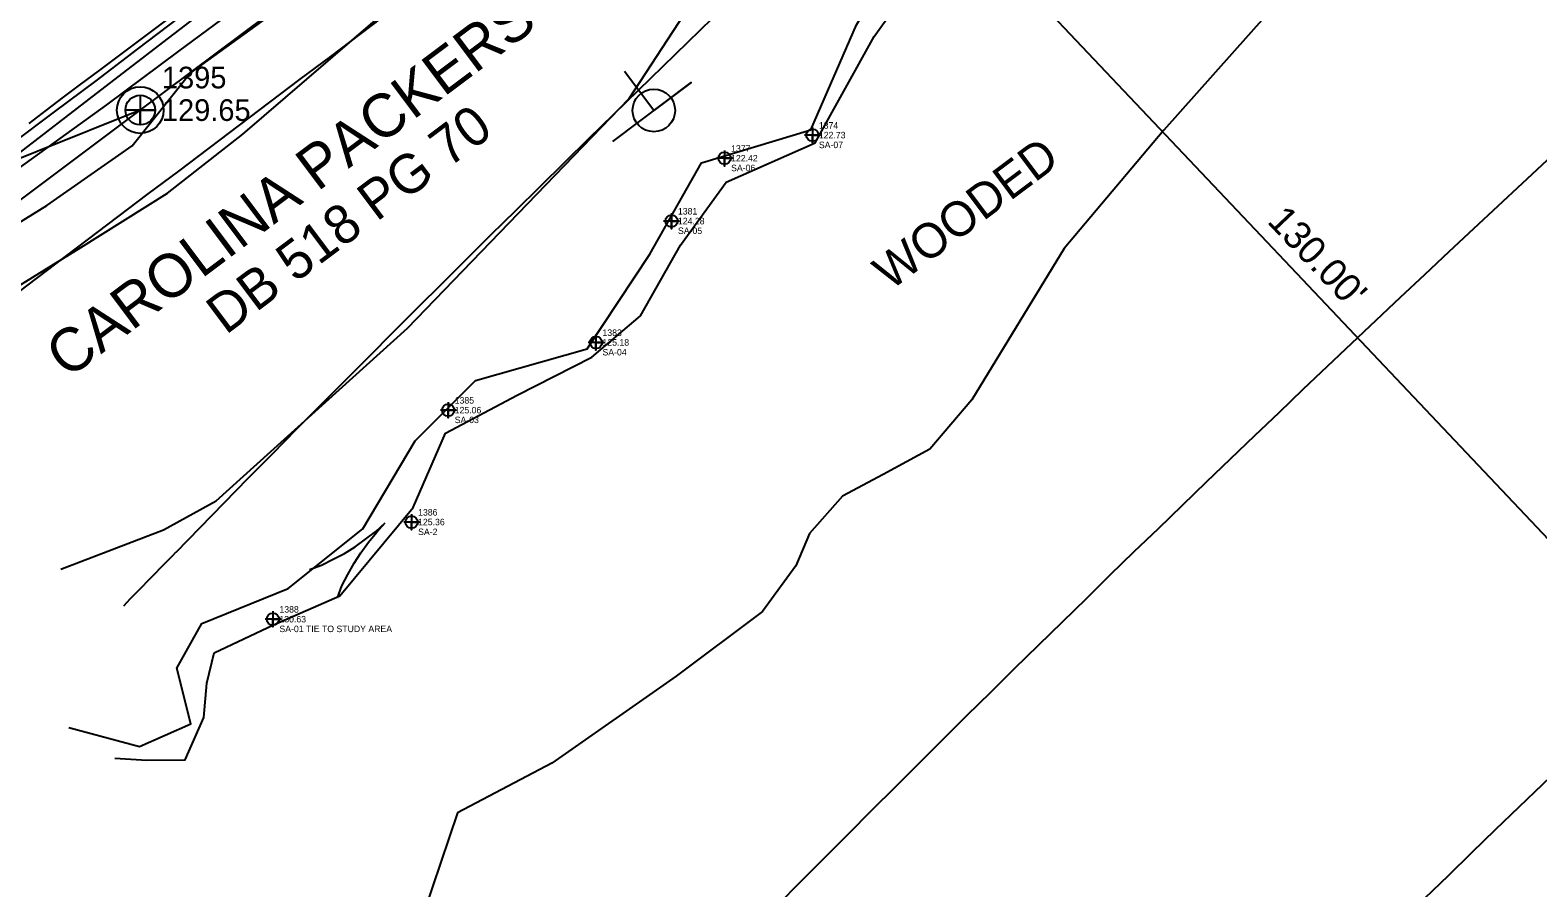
# Model space of a CAD drawing. Extents: x 2186615 to 2188822, y 629899 to 631820.
# Drawn here: x 2186940.8 to 2187114.7, y 630123.7 to 630222.6 of the extents above; entities that cross this region are included whole.
import ezdxf

# ---------------------------------------------------------------- set-up
doc = ezdxf.new("R2010")
doc.units = 0
for name, color, linetype in [('Exist Environmental Wetland Boundary Cogo Comment', 7, 'Continuous'), ('Exist Environmental Wetland Boundary Cogo Elevation', 7, 'Continuous'), ('Exist Environmental Wetland Boundary Cogo Number', 7, 'Continuous'), ('Exist Environmental Wetland Boundary Cogo Point CELL', 7, 'Continuous'), ('Exist Horizontal Alignment', 7, 'Continuous'), ('Exist Hydro Jurisdictional Stream or Body of Water', 7, 'Continuous'), ('Exist Hydro Stream Flow Arrow CELL', 7, 'Continuous'), ('Exist Property Deed Book Text', 7, 'Continuous'), ('Exist Property Owner Text', 7, 'Continuous'), ('Exist Right of Way Line', 7, 'Continuous'), ('Exist Right of Way Width CELL', 7, 'Continuous'), ('Exist Roads EOP', 7, 'Continuous'), ('Exist Roads EOT', 7, 'Continuous'), ('Exist Utilities Power Joint Use Telephone CELL', 7, 'Continuous'), ('Exist Utilities Sanitary Sewer Manhole CELL', 7, 'Continuous'), ('Exist Utilities Sanitary Sewer Manhole Cogo Elevation', 7, 'Continuous'), ('Exist Utilities Sanitary Sewer Manhole Cogo Number', 7, 'Continuous'), ('Exist Utilities Sanitary Sewer Manhole Leader', 7, 'Continuous'), ('Exist Utilities Sanitary Sewer UG Line', 7, 'Continuous'), ('Exist Utilities Telephone UG Cable SUE LOS C', 7, 'Continuous'), ('Exist Utilities Telephone UG FO SUE LOS B', 7, 'Continuous'), ('Exist Vegetation Woods Line', 7, 'Continuous'), ('Exist Vegetation Woods Line Text', 7, 'Continuous'), ('Scratch_Level_1', 7, 'Continuous')]:
    doc.layers.add(name, color=color, linetype=linetype)

msp = doc.modelspace()

# ---------------------------------------------------------------- linework, layer by layer
at = {"layer": 'Exist Environmental Wetland Boundary Cogo Point CELL'}
for points in [[(2187031.03, 630211.35), (2187031.03, 630209.56), (2187031.03, 630210.45), (2187031.93, 630210.45), (2187030.13, 630210.45)], [(2187020.91, 630208.69), (2187020.91, 630206.89), (2187020.91, 630207.79), (2187021.81, 630207.79), (2187020.01, 630207.79)], [(2187014.78, 630201.45), (2187014.78, 630199.65), (2187014.78, 630200.55), (2187015.68, 630200.55), (2187013.88, 630200.55)], [(2187006.08, 630187.45), (2187006.08, 630185.65), (2187006.08, 630186.55), (2187006.98, 630186.55), (2187005.18, 630186.55)], [(2186989.04, 630179.65), (2186989.04, 630177.85), (2186989.04, 630178.75), (2186989.94, 630178.75), (2186988.14, 630178.75)], [(2186984.82, 630166.74), (2186984.82, 630164.95), (2186984.82, 630165.84), (2186985.72, 630165.84), (2186983.92, 630165.84)], [(2186968.83, 630155.55), (2186968.83, 630153.75), (2186968.83, 630154.65), (2186969.73, 630154.65), (2186967.93, 630154.65)]]:
    msp.add_lwpolyline(points, dxfattribs=at)
for centre in [(2187031.03, 630210.45), (2187020.91, 630207.79), (2187014.78, 630200.55), (2187006.08, 630186.55), (2186989.04, 630178.75), (2186984.82, 630165.84), (2186968.83, 630154.65)]:
    msp.add_circle(centre, 0.703, dxfattribs=at)
at = {"layer": 'Exist Horizontal Alignment'}
msp.add_arc((2232330.7, 570095.74), 75342.48, 126.8592631, 127.0730198, dxfattribs=at)
at = {"layer": 'Exist Hydro Jurisdictional Stream or Body of Water'}
for points in [[(2186945.28, 630142.14), (2186953.45, 630139.97), (2186959.37, 630142.56), (2186957.75, 630149), (2186960.65, 630154.13), (2186970.58, 630158.18), (2186979.2, 630165.07), (2186985.24, 630175.2), (2186992.2, 630182.18), (2187005.05, 630185.83), (2187012.27, 630196.73), (2187018.23, 630207.27), (2187030.87, 630211.07), (2187036.12, 630223.16), (2187043.3, 630234.99), (2187052.05, 630246.59), (2187063.94, 630254.24), (2187079.12, 630254.94), (2187084.62, 630265.04), (2187091.95, 630272.3), (2187103.31, 630282.29), (2187113.92, 630297.14), (2187128.08, 630305.06)], [(2186950.59, 630138.61), (2186954.28, 630138.39), (2186958.71, 630138.41), (2186960.85, 630143.3), (2186961.21, 630147.28), (2186962.05, 630150.76), (2186968.9, 630153.99), (2186976.55, 630157.35), (2186984.99, 630167.53), (2186988.72, 630176.1), (2186996.99, 630180.49), (2187005.6, 630184.87), (2187011.23, 630189.6), (2187015.82, 630197.75), (2187021.08, 630205.03), (2187031.34, 630209.56), (2187038.17, 630221.84), (2187054.63, 630244.89)]]:
    msp.add_lwpolyline(points, dxfattribs=at)
at = {"layer": 'Exist Hydro Stream Flow Arrow CELL'}
msp.add_line((2186978.22, 630162.24), (2186978.22, 630162.24), dxfattribs=at)
for points in [[(2186973.05, 630160.37), (2186974.43, 630160.88), (2186975.77, 630161.55), (2186977.08, 630162.22), (2186978.31, 630162.99), (2186979.52, 630163.85), (2186980.69, 630164.77), (2186981.79, 630165.75)], [(2186976.26, 630157.1), (2186976.79, 630158.47), (2186977.48, 630159.8), (2186978.18, 630161.1), (2186978.97, 630162.31), (2186979.85, 630163.51), (2186980.8, 630164.67), (2186981.79, 630165.75)]]:
    msp.add_lwpolyline(points, dxfattribs=at)
at = {"layer": 'Exist Right of Way Line'}
for centre, radius, start, end in [((2189028.8, 628141.74), 2893.55, 125.65722, 135.70821), ((2189028.8, 628141.74), 2763.55, 125.65722, 135.70821), ((2232330.7, 570095.74), 75312.48, 126.8592631, 127.0730198), ((2188984.64, 628184.81), 2831.87, 135.70821, 135.88261)]:
    msp.add_arc(centre, radius, start, end, dxfattribs=at)
at = {"layer": 'Exist Right of Way Width CELL'}
for p in [(2187040.28, 630243.75), (2187129.62, 630149.31)]:
    msp.add_line(p, (2187087.53, 630193.8), dxfattribs=at)
at = {"layer": 'Exist Roads EOP'}
msp.add_lwpolyline([(2186957.96, 630223.97), (2186953.18, 630220.35), (2186948.4, 630216.73), (2186943.62, 630213.12), (2186938.82, 630209.52)], dxfattribs=at)
at = {"layer": 'Exist Roads EOT'}
msp.add_lwpolyline([(2186956.67, 630223.81), (2186954.67, 630222.31), (2186952.66, 630220.82), (2186950.66, 630219.32), (2186948.66, 630217.83), (2186946.66, 630216.33), (2186944.66, 630214.83), (2186942.67, 630213.32), (2186940.67, 630211.81)], dxfattribs=at)
at = {"layer": 'Exist Utilities Power Joint Use Telephone CELL'}
msp.add_line((2187012.75, 630213.3), (2187012.75, 630213.3), dxfattribs=at)
msp.add_lwpolyline([(2187008.03, 630209.7), (2187017.07, 630216.53), (2187012.76, 630213.28), (2187009.35, 630217.77)], dxfattribs=at)
msp.add_circle((2187012.75, 630213.3), 2.45, dxfattribs=at)
at = {"layer": 'Exist Utilities Sanitary Sewer Manhole CELL'}
msp.add_lwpolyline([(2186953.53, 630215.05), (2186953.53, 630211.63), (2186953.53, 630213.34), (2186955.24, 630213.34), (2186951.81, 630213.34)], dxfattribs=at)
for radius in [2.69, 1.71]:
    msp.add_circle((2186953.53, 630213.34), radius, dxfattribs=at)
at = {"layer": 'Exist Utilities Sanitary Sewer Manhole Leader'}
msp.add_lwpolyline([(2186953.53, 630213.34), (2186905.97, 630194.25), (2186869.08, 630166.59)], dxfattribs=at)
at = {"layer": 'Exist Utilities Sanitary Sewer UG Line'}
for p, q in [((2186953.53, 630213.34), (2187280.26, 630457.75)), ((2186647.85, 629984.07), (2186953.53, 630213.34))]:
    msp.add_line(p, q, dxfattribs=at)
at = {"layer": 'Exist Utilities Telephone UG Cable SUE LOS C'}
for points in [[(2186925.08, 630191.44), (2186942.75, 630202.33), (2186952.61, 630209.21), (2186959.24, 630217.54), (2186981.1, 630233.4), (2186988.91, 630240.52)], [(2186929.03, 630186.19), (2186933.47, 630189.36), (2186946.68, 630197.49), (2186956.69, 630203.77), (2186965.35, 630210.55), (2186985.31, 630227.73), (2186993.86, 630234.89)]]:
    msp.add_lwpolyline(points, dxfattribs=at)
at = {"layer": 'Exist Utilities Telephone UG FO SUE LOS B'}
for points in [[(2186921.88, 630195.7), (2186938.73, 630207.73), (2186949, 630215.65), (2186956.78, 630221.62), (2186978.08, 630237.97), (2186986.3, 630243.89)], [(2186922.89, 630194.36), (2186939.61, 630206.67), (2186949.68, 630213.94), (2186957.97, 630220.12), (2186979.26, 630235.89), (2186987.51, 630242.36)]]:
    msp.add_lwpolyline(points, dxfattribs=at)
at = {"layer": 'Exist Vegetation Woods Line'}
for points in [[(2187134.59, 630271.74), (2187127.09, 630263.84), (2187118.72, 630254.03), (2187108.35, 630244.63), (2187099.34, 630237.49), (2187083.15, 630224.07), (2187071.54, 630211.01), (2187060.06, 630197.38), (2187049.4, 630179.92), (2187044.57, 630174.23), (2187039.19, 630171.31), (2187034.5, 630168.82), (2187030.7, 630164.51), (2187029.13, 630160.78), (2187025.28, 630155.53), (2187015.34, 630148.08), (2187000.99, 630138.03), (2186990.13, 630132.3), (2186985.3, 630118.09)], [(2186944.38, 630160.41), (2186956.2, 630164.93), (2186962.27, 630168.27), (2186984.34, 630188.21), (2187009.89, 630214.68), (2187023.3, 630235.22), (2187047.5, 630258.38), (2187065.13, 630270.94)]]:
    msp.add_lwpolyline(points, dxfattribs=at)
at = {"layer": 'Scratch_Level_1'}
msp.add_arc((2189028.8, 628141.74), 2815.55, 125.65722, 135.70821, dxfattribs=at)

# ---------------------------------------------------------------- texts
at = {"layer": 'Exist Environmental Wetland Boundary Cogo Comment'}
for s, p in [('SA-07', (2187031.78, 630208.95)), ('SA-06', (2187021.66, 630206.29)), ('SA-05', (2187015.53, 630199.05)), ('SA-04', (2187006.83, 630185.05)), ('SA-03', (2186989.79, 630177.25)), ('SA-2', (2186985.57, 630164.34)), ('SA-01 TIE TO STUDY AREA', (2186969.58, 630153.15))]:
    msp.add_text(s, height=0.75, dxfattribs=at).set_placement(p)
at = {"layer": 'Exist Environmental Wetland Boundary Cogo Elevation'}
for s, p in [('122.73', (2187031.78, 630210.08)), ('122.42', (2187021.66, 630207.42)), ('124.28', (2187015.53, 630200.17)), ('125.18', (2187006.83, 630186.18)), ('125.06', (2186989.79, 630178.37)), ('125.36', (2186985.57, 630165.47)), ('130.63', (2186969.58, 630154.27))]:
    msp.add_text(s, height=0.75, dxfattribs=at).set_placement(p)
at = {"layer": 'Exist Environmental Wetland Boundary Cogo Number'}
for s, p in [('1374', (2187031.78, 630211.2)), ('1377', (2187021.66, 630208.54)), ('1381', (2187015.53, 630201.3)), ('1383', (2187006.83, 630187.3)), ('1385', (2186989.79, 630179.5)), ('1386', (2186985.57, 630166.59)), ('1388', (2186969.58, 630155.4))]:
    msp.add_text(s, height=0.75, dxfattribs=at).set_placement(p)
at = {"layer": 'Exist Property Deed Book Text'}
msp.add_text('DB 518 PG 70', height=4.5, rotation=36.8593, dxfattribs=at).set_placement((2186963.39, 630187.36))
at = {"layer": 'Exist Property Owner Text'}
msp.add_text('CAROLINA PACKERS INC', height=5, rotation=36.8593, dxfattribs=at).set_placement((2186945.13, 630182.26))
at = {"layer": 'Exist Right of Way Width CELL'}
msp.add_text("130.00'", height=3.2, rotation=313.4107, dxfattribs=at).set_placement((2187083.36, 630200.43))
at = {"layer": 'Exist Utilities Sanitary Sewer Manhole Cogo Elevation'}
msp.add_text('129.65', height=2.5, dxfattribs=at).set_placement((2186956.03, 630212.09))
at = {"layer": 'Exist Utilities Sanitary Sewer Manhole Cogo Number'}
msp.add_text('1395', height=2.5, dxfattribs=at).set_placement((2186956.03, 630215.84))
at = {"layer": 'Exist Vegetation Woods Line Text'}
msp.add_text('WOODED', height=4, rotation=36.8593, dxfattribs=at).set_placement((2187040.03, 630192.46))

doc.saveas('drawing.dxf')
